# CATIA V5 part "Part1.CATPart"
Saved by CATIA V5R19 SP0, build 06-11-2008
Part number: Part1
Bounding box of the stored display mesh (mm): x -100 to 100, y -54.891 to 54.891, z 0 to 20
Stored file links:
  D:\Shriniwas\v5_r19\c16_CAT_v5r19\c16_Part\Roll curve Joint\Part1.CATPart
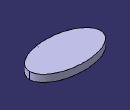
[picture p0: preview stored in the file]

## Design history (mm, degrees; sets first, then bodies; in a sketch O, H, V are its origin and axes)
Body1 (main body)
  Sketch1 on xy-plane, origin (0, 0, 0), H (1, 0, 0), V (0, 1, 0)
    point P1 (0, 0)
    ellipse A1 centre (0, 0) semi-axes 100, 55 rotation 0
    "Radius" A1 = 100
    "Radius" A1 = 55
    angle V A1 = 90
    coincidence: P1 H, P1 V
  Pad1: profile Sketch1, direction (0, 0, 1), length 20
  Point1: type OnCurve, Support edge [face of Pad1 from Sketch1.A1 | end face of Pad1], Length 344.171, RefPoint {extremum Reference edge [face of Pad1 from Sketch1.A1 | end face of Pad1], Direction (1, 2, 3)}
